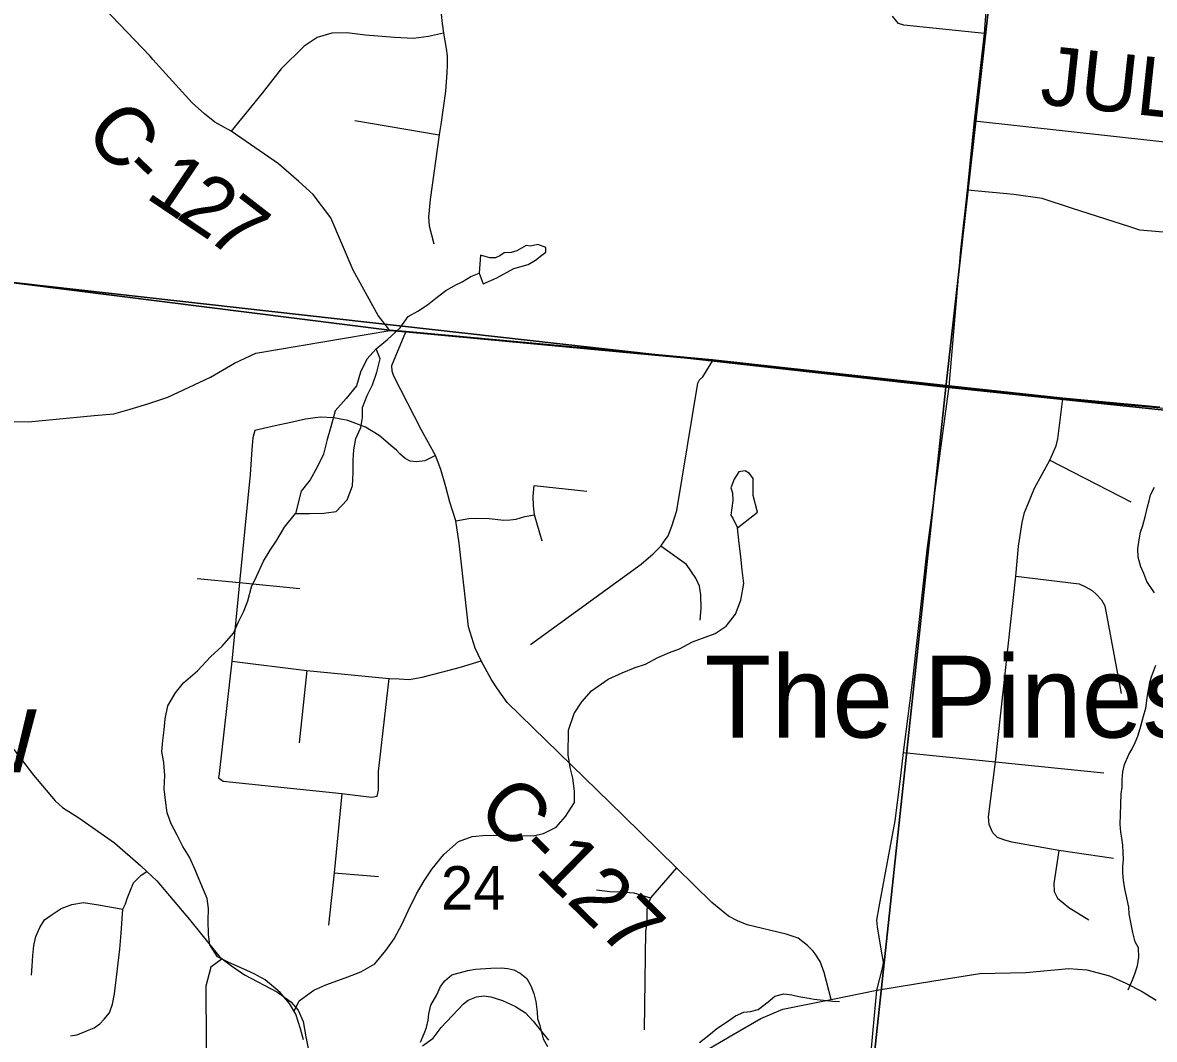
# Model space of a CAD drawing. Extents: x 0 to 34, y -2 to 22.
# Drawn here: x 3.329 to 4.421, y 17.226 to 18.207 of the extents above; entities that cross this region are included whole.
import ezdxf

# ---------------------------------------------------------------- set-up
doc = ezdxf.new("R2010")
doc.units = 0
for name, color, linetype in [('GM_X_County_Road', 7, 'Continuous'), ('GM_X_County_Road_Text', 7, 'Continuous'), ('GM_X_Minor_Lake', 7, 'Continuous'), ('GM_X_Minor_River', 7, 'Continuous'), ('GM_X_Rail_Line', 7, 'Continuous'), ('GM_X_Section', 7, 'Continuous'), ('GM_X_Section_Text', 7, 'Continuous'), ('GM_X_Township_Road', 7, 'Continuous'), ('GM_X_Unincorporated_Text', 7, 'Continuous')]:
    doc.layers.add(name, color=color, linetype=linetype)

msp = doc.modelspace()

# ---------------------------------------------------------------- linework, layer by layer
at = {"layer": 'GM_X_County_Road'}
msp.add_line((3.6834, 17.9102), (3.699, 17.9089), dxfattribs=at)
for points in [[(4.2476, 18.1125), (4.257, 18.1969), (4.2646, 18.2964), (4.2809, 18.4508), (4.2845, 18.4827), (4.309, 18.6761), (4.321, 18.7984), (4.3234, 18.8215)], [(3.4549, 18.1718), (3.4521, 18.1749), (3.4075, 18.2217), (3.3688, 18.2666), (3.3673, 18.2678), (3.3628, 18.2699), (3.3411, 18.2766), (3.3169, 18.29)], [(3.6834, 17.9102), (3.6723, 17.9249), (3.6479, 17.9687), (3.6264, 18.0192), (3.6096, 18.0417), (3.5957, 18.0541), (3.5761, 18.0711), (3.5305, 18.1027), (3.5147, 18.1112), (3.5046, 18.1194), (3.4927, 18.1301), (3.4549, 18.1718)], [(4.2231, 17.8563), (4.2342, 17.9883), (4.2406, 18.0456), (4.2476, 18.1125)], [(4.2476, 18.1125), (4.466, 18.0886), (4.758, 18.0581)], [(3.3142, 17.8225), (3.3348, 17.8222), (3.3981, 17.8284), (3.4172, 17.8299), (3.4328, 17.8343), (3.4499, 17.8395), (3.4692, 17.846), (3.5105, 17.8653), (3.5336, 17.8787), (3.5541, 17.8883), (3.6834, 17.9102)], [(4.1093, 17.2649), (4.1025, 17.2909), (4.0986, 17.3016), (4.0938, 17.309), (4.0917, 17.3113), (4.0864, 17.317), (4.0775, 17.3239), (4.0658, 17.3277), (4.0281, 17.3369), (4.0187, 17.3407), (4.01, 17.3452), (3.994, 17.3585), (3.9601, 17.3917), (3.9086, 17.4423), (3.7965, 17.5513), (3.7873, 17.5644), (3.7811, 17.574), (3.7716, 17.5915), (3.7658, 17.6039), (3.7594, 17.6245), (3.7503, 17.7051), (3.7472, 17.7266), (3.7414, 17.7447), (3.7373, 17.7594), (3.7326, 17.7761), (3.7276, 17.7897), (3.7139, 17.814), (3.6874, 17.8662), (3.6856, 17.8711), (3.6853, 17.8764), (3.699, 17.9089)], [(3.699, 17.9089), (3.9116, 17.8892), (3.995, 17.8815), (4.2231, 17.8563), (4.3328, 17.8445), (4.4265, 17.8357), (4.5119, 17.8261), (4.6385, 17.8125), (4.7305, 17.8021), (4.8416, 17.7902), (4.8921, 17.785), (5.1052, 17.7555), (5.1438, 17.7513), (5.1995, 17.7504), (5.2414, 17.7441), (5.2926, 17.7419), (5.3775, 17.7381), (5.4364, 17.7355), (5.4969, 17.7336), (5.5492, 17.7321), (5.6317, 17.7272), (5.6868, 17.7254)], [(4.1357, 17.0618), (4.1445, 17.1843), (4.147, 17.2076), (4.1533, 17.2738), (4.1587, 17.295), (4.1597, 17.3001), (4.1595, 17.3027), (4.1576, 17.3113), (4.1539, 17.3349), (4.1534, 17.3381), (4.1533, 17.3414), (4.1555, 17.3542), (4.171, 17.4373), (4.1756, 17.4751), (4.1791, 17.5032), (4.188, 17.5731), (4.2018, 17.6987), (4.2231, 17.8563)], [(3.3111, 17.5186), (3.3398, 17.4812), (3.3605, 17.4565), (3.3676, 17.4502), (3.3833, 17.44), (3.4177, 17.4158), (3.4433, 17.3936), (3.4491, 17.3882), (3.4586, 17.3792), (3.49, 17.3421), (3.5195, 17.3055), (3.5217, 17.3039), (3.5307, 17.2973), (3.5431, 17.2886), (3.5749, 17.272), (3.588, 17.2626), (3.595, 17.2545), (3.5997, 17.2434), (3.6024, 17.2289), (3.6069, 17.2061)], [(4.1093, 17.2649), (4.1533, 17.2738), (4.2082, 17.2829), (4.2527, 17.2899), (4.2971, 17.2908), (4.3385, 17.2948), (4.3559, 17.2933), (4.3778, 17.2875), (4.3936, 17.2804), (4.4086, 17.2728), (4.4228, 17.2642)], [(3.7149, 17.22), (3.7253, 17.2274), (3.7331, 17.2379), (3.7544, 17.2605), (3.7591, 17.2642), (3.7671, 17.2674), (3.7741, 17.2682), (3.7808, 17.2675), (3.7921, 17.2639), (3.8048, 17.2579), (3.8142, 17.252), (3.8216, 17.2439), (3.8364, 17.2254)], [(4.052, 17.2508), (4.0627, 17.2553), (4.1093, 17.2649)], [(3.9828, 17.2123), (4.0147, 17.231), (4.0412, 17.2463), (4.052, 17.2508)]]:
    msp.add_lwpolyline(points, dxfattribs=at)
at = {"layer": 'GM_X_Minor_Lake'}
for points in [[(3.7697, 17.9655), (3.7736, 17.9555), (3.7867, 17.9613), (3.8029, 17.97), (3.817, 17.9741), (3.824, 17.9781), (3.8302, 17.9829), (3.834, 17.9858), (3.8338, 17.9904), (3.8263, 17.9933), (3.819, 17.9916), (3.8149, 17.9924), (3.806, 17.9873), (3.8006, 17.9856), (3.7938, 17.9854), (3.7895, 17.9825), (3.7853, 17.9803), (3.78, 17.9804), (3.7709, 17.983)], [(3.7709, 17.983), (3.7697, 17.9655)], [(3.5925, 17.7337), (3.606, 17.7337), (3.6197, 17.7341), (3.6315, 17.7357), (3.6424, 17.7468), (3.6473, 17.7603), (3.6481, 17.7732), (3.648, 17.785), (3.6487, 17.7952), (3.6505, 17.8062), (3.6553, 17.8167), (3.6571, 17.8265), (3.657, 17.836), (3.6614, 17.8477), (3.6666, 17.8578), (3.6708, 17.8702), (3.6741, 17.883), (3.6702, 17.8926), (3.6612, 17.8826), (3.6552, 17.8702), (3.6511, 17.857), (3.6412, 17.8448), (3.6307, 17.8329), (3.6265, 17.8174), (3.6231, 17.805), (3.6193, 17.7911), (3.6133, 17.7783), (3.6065, 17.7663), (3.5979, 17.7552)], [(4.0188, 17.72), (4.0381, 17.7351), (4.0339, 17.7512), (4.034, 17.7675), (4.0303, 17.7722), (4.0262, 17.7749), (4.0201, 17.774), (4.0157, 17.7669), (4.0125, 17.7586), (4.0139, 17.7536), (4.0144, 17.7464), (4.0135, 17.7392), (4.0125, 17.732), (4.0144, 17.7293)], [(3.5979, 17.7552), (3.5925, 17.7337)], [(4.0144, 17.7293), (4.0188, 17.72)]]:
    msp.add_lwpolyline(points, dxfattribs=at)
at = {"layer": 'GM_X_Minor_River'}
for points in [[(3.6702, 17.8926), (3.6811, 17.9018), (3.6935, 17.9129), (3.701, 17.9237), (3.7103, 17.9291), (3.7199, 17.935), (3.7277, 17.9416), (3.7374, 17.9489), (3.7478, 17.9547), (3.7532, 17.9572), (3.7617, 17.9623), (3.7697, 17.9655)], [(4.4211, 17.6572), (4.4137, 17.668), (4.4108, 17.676), (4.4079, 17.6822), (4.4054, 17.6917), (4.4051, 17.6997), (4.4064, 17.7084), (4.4077, 17.7156), (4.4097, 17.7221), (4.4122, 17.7304), (4.4143, 17.7402), (4.4159, 17.7459), (4.4171, 17.7516), (4.4211, 17.7591)], [(3.6001, 17.2258), (3.5973, 17.2365), (3.5928, 17.2506), (3.5866, 17.261), (3.5777, 17.2715), (3.5632, 17.2836), (3.5524, 17.2896), (3.5419, 17.2944), (3.528, 17.3005), (3.5171, 17.3061), (3.5098, 17.3176), (3.5086, 17.3276), (3.5081, 17.3409), (3.5084, 17.3526), (3.5072, 17.3621), (3.5011, 17.3767), (3.4957, 17.3898), (3.49, 17.4021), (3.4838, 17.4125), (3.4784, 17.4233), (3.4726, 17.4344), (3.4687, 17.4448), (3.4671, 17.457), (3.4658, 17.468), (3.4665, 17.4809), (3.4653, 17.4935), (3.4633, 17.5041), (3.4644, 17.5148), (3.4658, 17.525), (3.4668, 17.5356), (3.4694, 17.5481), (3.4765, 17.5608), (3.4844, 17.5705), (3.4979, 17.5819), (3.5104, 17.5953), (3.5217, 17.6056), (3.5326, 17.6182), (3.5375, 17.6291), (3.5427, 17.6396), (3.5463, 17.6494), (3.5501, 17.663), (3.5549, 17.6728), (3.5617, 17.6878), (3.5681, 17.6983), (3.5744, 17.708), (3.5819, 17.7207), (3.5925, 17.7337)], [(3.591, 17.2535), (3.5961, 17.2635), (3.61, 17.2737), (3.6216, 17.2788), (3.6334, 17.283), (3.643, 17.2866), (3.6553, 17.2916), (3.6688, 17.2992), (3.6797, 17.3122), (3.6876, 17.3234), (3.6952, 17.3377), (3.7012, 17.3504), (3.7092, 17.3666), (3.7167, 17.3793), (3.7242, 17.3909), (3.7356, 17.4047), (3.7496, 17.4172), (3.763, 17.4222), (3.7767, 17.4234), (3.7896, 17.4231), (3.801, 17.4235), (3.8108, 17.4229), (3.8218, 17.4226), (3.8317, 17.425), (3.844, 17.4312), (3.853, 17.4412), (3.8617, 17.455), (3.8616, 17.4657), (3.86, 17.4783), (3.8573, 17.4886), (3.8553, 17.5008), (3.8559, 17.5247), (3.8613, 17.5409), (3.8688, 17.5521), (3.8781, 17.5625), (3.894, 17.5739), (3.9074, 17.58), (3.9201, 17.585), (3.93, 17.5885), (3.9419, 17.5947), (3.9531, 17.5997), (3.963, 17.6033), (3.9754, 17.6098), (3.9876, 17.6144), (3.9972, 17.618), (4.008, 17.6249), (4.017, 17.6365), (4.0219, 17.65), (4.025, 17.6663), (4.0234, 17.6789), (4.0219, 17.6922), (4.0203, 17.7048), (4.0188, 17.72)], [(4.3958, 17.2741), (4.4002, 17.2843), (4.4026, 17.2904), (4.4047, 17.2972), (4.4059, 17.3055), (4.4057, 17.3146), (4.4024, 17.3204), (4.4003, 17.3295), (4.3982, 17.3391), (4.3968, 17.3475), (4.3965, 17.3539), (4.3937, 17.3658), (4.3926, 17.3715), (4.3913, 17.3799), (4.3906, 17.3871), (4.3907, 17.3932), (4.3913, 17.4), (4.391, 17.4065), (4.3907, 17.4137), (4.3897, 17.4206), (4.3887, 17.4263), (4.3881, 17.4339), (4.3882, 17.443), (4.389, 17.4632), (4.3898, 17.4696), (4.39, 17.4768), (4.3905, 17.4844), (4.3922, 17.4916), (4.3965, 17.5011), (4.3997, 17.5067), (4.4025, 17.5127), (4.4049, 17.5188), (4.4073, 17.5263), (4.4106, 17.5381), (4.4126, 17.546), (4.4144, 17.5581), (4.4157, 17.5653), (4.4165, 17.571), (4.4185, 17.5771), (4.4225, 17.5873)], [(3.7129, 17.2236), (3.7165, 17.2319), (3.7189, 17.2376), (3.7205, 17.2448), (3.721, 17.2508), (3.7231, 17.2592), (3.7286, 17.2693), (3.7322, 17.2772), (3.7365, 17.2829), (3.7431, 17.2885), (3.7588, 17.2927), (3.7661, 17.2941), (3.781, 17.295), (3.7909, 17.2952), (3.7974, 17.2947), (3.8031, 17.2935), (3.8092, 17.2903), (3.8156, 17.2849), (3.8193, 17.278), (3.8222, 17.2707), (3.8243, 17.2627), (3.8257, 17.2524)], [(3.9821, 17.2234), (3.9929, 17.2315), (3.9988, 17.2367), (4.0092, 17.2434), (4.0169, 17.249), (4.025, 17.2526), (4.0315, 17.2533), (4.0388, 17.255), (4.0485, 17.2625), (4.0547, 17.2681), (4.0635, 17.2702), (4.0711, 17.2693), (4.078, 17.2676), (4.0856, 17.2664), (4.0928, 17.2651), (4.0986, 17.2646), (4.105, 17.2637), (4.1108, 17.2633), (4.1172, 17.2628)], [(3.8257, 17.2524), (3.8259, 17.2463), (3.8281, 17.2398), (3.8313, 17.2268), (3.8354, 17.2195)]]:
    msp.add_lwpolyline(points, dxfattribs=at)
at = {"layer": 'GM_X_Rail_Line'}
for points in [[(4.4263, 17.8362), (4.3326, 17.8451), (4.2228, 17.8568), (3.9947, 17.882), (3.9114, 17.8897), (3.6988, 17.9094), (3.6832, 17.9108), (3.2869, 17.9604)], [(3.2869, 17.9604), (3.6832, 17.9108), (3.6988, 17.9094), (3.9114, 17.8897), (3.9947, 17.882), (4.2228, 17.8568), (4.3326, 17.8451), (4.4263, 17.8362)]]:
    msp.add_lwpolyline(points, dxfattribs=at)
at = {"layer": 'GM_X_Section'}
for points in [[(4.3356, 18.8839), (4.2197, 17.8557), (3.2914, 17.96), (3.3818, 18.9832)], [(4.3356, 18.8839), (5.3451, 18.7715), (5.25, 17.7471), (4.2197, 17.8557)], [(4.2197, 17.8557), (4.1192, 16.9159), (3.2017, 16.9647), (3.2914, 17.96)], [(5.25, 17.7471), (5.1427, 16.732), (4.1192, 16.9159), (4.2197, 17.8557)]]:
    msp.add_lwpolyline(points, close=True, dxfattribs=at)
at = {"layer": 'GM_X_Township_Road'}
for p, q in [((3.6495, 18.1129), (3.731, 18.0991)), ((4.3201, 17.7851), (4.3984, 17.745)), ((3.6035, 17.5824), (3.5958, 17.5124)), ((3.6297, 17.3871), (3.6724, 17.3836))]:
    msp.add_line(p, q, dxfattribs=at)
for points in [[(3.7327, 18.2632), (3.7301, 18.2453), (3.7315, 18.2274), (3.734, 18.2065)], [(4.257, 18.1969), (4.1793, 18.2048), (4.1741, 18.2067), (4.1685, 18.2137)], [(3.734, 18.2065), (3.7351, 18.1971), (3.7377, 18.1825), (3.7388, 18.1753), (3.7386, 18.1666), (3.7385, 18.159), (3.737, 18.1412), (3.7325, 18.1092)], [(3.7351, 18.1971), (3.7206, 18.1941), (3.7061, 18.192), (3.688, 18.1931), (3.66, 18.1952), (3.6419, 18.1974), (3.6274, 18.1971), (3.6132, 18.1931), (3.6009, 18.1847), (3.5787, 18.1629), (3.5602, 18.1393), (3.5305, 18.1027)], [(3.7325, 18.1092), (3.7317, 18.1034), (3.731, 18.0991), (3.7222, 18.0368), (3.7207, 18.0198), (3.7213, 18.0114), (3.7258, 17.9939)], [(4.4557, 18.0029), (4.4071, 18.0073), (4.3964, 18.0107), (4.3822, 18.0151), (4.3409, 18.0285), (4.3126, 18.0377), (4.2853, 18.0414), (4.2406, 18.0456)], [(3.819, 17.6074), (3.9258, 17.6849), (3.9374, 17.6948), (3.945, 17.7022), (3.9483, 17.7074), (3.9518, 17.7123), (3.9555, 17.7214), (3.9602, 17.7367), (3.9804, 17.8594), (3.9823, 17.8628), (3.9854, 17.8657), (3.995, 17.8815)], [(4.3814, 17.4009), (4.3288, 17.4086), (4.2836, 17.4166), (4.2758, 17.419), (4.2696, 17.4212), (4.265, 17.4255), (4.2616, 17.4335), (4.2611, 17.4409), (4.2676, 17.4941), (4.2874, 17.6733), (4.2898, 17.7023), (4.2935, 17.7251), (4.2958, 17.7347), (4.2982, 17.7408), (4.3052, 17.7582), (4.3201, 17.7851), (4.3262, 17.7989), (4.328, 17.8057), (4.3328, 17.8445)], [(3.7276, 17.7897), (3.7173, 17.7847), (3.7093, 17.7837), (3.7029, 17.7843), (3.6981, 17.7868), (3.6932, 17.7913), (3.6899, 17.7948), (3.6862, 17.7979), (3.6732, 17.8091), (3.66, 17.8171), (3.6429, 17.8235), (3.6293, 17.8262), (3.6161, 17.8266), (3.602, 17.8249), (3.5878, 17.8214), (3.5728, 17.8183), (3.5616, 17.8159), (3.5532, 17.8138), (3.5513, 17.8066), (3.5504, 17.7956), (3.5486, 17.7715), (3.5385, 17.6672), (3.5309, 17.5913), (3.5187, 17.4828), (3.5182, 17.4786), (3.5226, 17.4754), (3.6371, 17.4636), (3.6656, 17.4601), (3.6711, 17.461), (3.6724, 17.4667), (3.6725, 17.4849), (3.6827, 17.5746)], [(3.8305, 17.707), (3.8231, 17.7323), (3.8221, 17.741), (3.8217, 17.7505), (3.8227, 17.7606), (3.8736, 17.7552)], [(3.7472, 17.7266), (3.7596, 17.7288), (3.766, 17.7292), (3.7792, 17.729), (3.7934, 17.7274), (3.7996, 17.7276), (3.8054, 17.7284), (3.8138, 17.7307), (3.8231, 17.7323)], [(3.9829, 17.6309), (3.9839, 17.642), (3.9835, 17.6552), (3.9821, 17.6635), (3.9786, 17.6713), (3.9697, 17.6845), (3.945, 17.7022)], [(3.4977, 17.6709), (3.5385, 17.6672), (3.5967, 17.6614)], [(4.2874, 17.6733), (4.3485, 17.6659), (4.3547, 17.663), (4.3609, 17.6594), (4.3653, 17.6555), (4.3699, 17.6504), (4.3731, 17.6447), (4.3891, 17.5602)], [(3.5309, 17.5913), (3.6035, 17.5824), (3.6827, 17.5746), (3.6923, 17.5742), (3.702, 17.5737), (3.7146, 17.5757), (3.7333, 17.5806), (3.7516, 17.5853), (3.7716, 17.5915)], [(4.1791, 17.5032), (4.2676, 17.4941), (4.3722, 17.4834)], [(3.6371, 17.4636), (3.6297, 17.3871), (3.6243, 17.3366)], [(4.3288, 17.4086), (4.324, 17.3766), (4.3244, 17.3689), (4.3274, 17.3626), (4.3384, 17.3536), (4.3577, 17.3415)], [(3.3753, 17.2297), (3.3816, 17.2308), (3.3871, 17.2329), (3.3917, 17.2347), (3.3982, 17.2374), (3.4035, 17.2413), (3.4077, 17.2457), (3.4129, 17.2519), (3.4158, 17.2602), (3.4179, 17.2702), (3.4206, 17.2945), (3.4228, 17.3133), (3.4243, 17.3288), (3.4257, 17.3519), (3.4284, 17.3572), (3.43, 17.3623), (3.4331, 17.3703), (3.4362, 17.3772), (3.4408, 17.3821), (3.4435, 17.3848), (3.4491, 17.3882)], [(3.9601, 17.3917), (3.935, 17.3628), (3.9312, 17.352), (3.9314, 17.3386), (3.9301, 17.3303), (3.9287, 17.2355)], [(3.8827, 17.3705), (3.8958, 17.369), (3.9065, 17.3686), (3.9189, 17.3678), (3.935, 17.3628)], [(3.3377, 17.2884), (3.3383, 17.297), (3.3391, 17.3073), (3.3399, 17.3168), (3.342, 17.3257), (3.3459, 17.3341), (3.3503, 17.3415), (3.3568, 17.3461), (3.3663, 17.3527), (3.3766, 17.3566), (3.388, 17.3583), (3.4024, 17.356), (3.4257, 17.3519)], [(3.5217, 17.3039), (3.5106, 17.2961), (3.506, 17.2775), (3.506, 17.2627), (3.5063, 17.2381), (3.5067, 17.1462), (3.5065, 17.1086), (3.5046, 17.095), (3.5009, 17.0859), (3.4949, 17.0758), (3.4886, 17.068), (3.4541, 17.0387)]]:
    msp.add_lwpolyline(points, dxfattribs=at)

# ---------------------------------------------------------------- texts
at = {"layer": 'GM_X_County_Road_Text'}
for s, height, rotation, p in [('JULMAR RD', 0.05682, 353.9278, (4.3096, 18.1289)), ('C', 0.0568, 311.7299, (3.3871, 18.1004)), ('-', 0.0568, 316.0318, (3.4214, 18.0622)), ('1', 0.0568, 325.9496, (3.4465, 18.0393)), ('2', 0.0568, 326.1697, (3.4757, 18.0196)), ('7', 0.0568, 322.2204, (3.504, 18.0007)), ('C-127', 0.05682, 315.5865, (3.7653, 17.4453))]:
    msp.add_text(s, height=height, rotation=rotation, dxfattribs=at).set_placement(p)
at = {"layer": 'GM_X_Section_Text'}
msp.add_text('24', height=0.04186, rotation=0, dxfattribs=at).set_placement((3.7327, 17.3516))
at = {"layer": 'GM_X_Unincorporated_Text'}
for s, p in [('The Pines', (3.9869, 17.5175)), ('Mountview', (2.8377, 17.4841))]:
    msp.add_text(s, height=0.07898, rotation=0, dxfattribs=at).set_placement(p)

doc.saveas('drawing.dxf')
